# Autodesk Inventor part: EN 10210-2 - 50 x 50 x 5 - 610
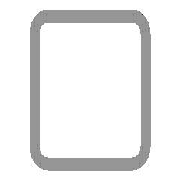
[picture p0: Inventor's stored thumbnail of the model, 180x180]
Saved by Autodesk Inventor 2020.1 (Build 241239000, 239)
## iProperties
IsCustomPart: 1
Created: 2019-01
Part Number: EN 10210-2 - 50 x 50 x 5 - 610
Material: Stahl, weich
Description: Rohrleitung
Document SubType Name: Modeling
Standard: DIN
Designer: lutzd
Standard Revision: 2006-07
Standards Organization: DIN
Language: de-DE
Size Designation: 50 x 50 x 5
Categories: <MemberInstance><Categories><Category DisplayName="Profile" InternalName="089c4875-fa83-4c05-b084-43b9cc11f5ed" Mnemonic="GRDR"><CategoryParameter DisplayName="
Stock Number: 50 x 50 x 5
Mass: 4175.75 g
Surface Area: 2083.96 cm^2
Volume: 531.943 cm^3
Density: 7.85 g/cm^3
Appearance: Halbpoliert
_CCFamilyMember: 16
_CCFamilyDisplayName: DIN EN 10210-2 (USAS B17.1 quadratisch) - Rohrleitung — In Klammern angegebene Größen wurden aufgehoben
_FrameMemberDoc: Frame Member File
_Version: 15.0.0
_GetPNFromCC: 1
G_L: 610,000 mm
G_W: 50,000 mm
G_H: 50,000 mm
DocNumber: ADSK-014142
Folder: .
Dimensions: 50x50x610 mm
Mass: 4,176 kg
+F1DF09DF-1374-4674-A909-8C9C65E2400E+SCHNITTDETAIL1: Schnittwinkel 90,00 grd
Title: Profil-Bauteil
Author: lutzd
Revision Number: -
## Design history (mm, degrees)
node "Startebene"
node "Endebene"
sketch "Skizze"
  geometry: L1 (-25, -17.5)-(-25, 17.5); L2 (-17.5, 25)-(17.5, 25); L3 (25, 17.5)-(25, -17.5); L4 (17.5, -25)-(-17.5, -25); L5 (-15, 20)-(15, 20); L6 (20, 15)-(20, -15); L7 (15, -20)-(-15, -20); L8 (-20, -15)-(-20, 15); L9 (0, 37.175)-(0, -37.175) reference; L10 (-37.175, 0)-(37.175, 0) reference; A1 r 7.5 centre (-17.5, -17.5) between (-25, -17.5) and (-17.5, -25); A2 r 7.5 centre (-17.5, 17.5) between (-17.5, 25) and (-25, 17.5); A3 r 7.5 centre (17.5, 17.5) between (25, 17.5) and (17.5, 25); A4 r 7.5 centre (17.5, -17.5) between (17.5, -25) and (25, -17.5); A5 r 5 centre (-15, -15) between (-20, -15) and (-15, -20); A6 r 5 centre (-15, 15) between (-15, 20) and (-20, 15); A7 r 5 centre (15, 15) between (20, 15) and (15, 20); A8 r 5 centre (15, -15) between (15, -20) and (20, -15)
  constraints: 16 end point, 16 point on circle, 16 tangent, 8 centre point, 6 equal radius, 4 parallel, 2 perpendicular, 2 other
  dimensions: "d7" = 7.5 radius of A1 (= G_IR); "d10" = 50 distance between parallel lines of L2 L4 (= G_H); "d11" = 50 distance between parallel lines of L1 L3 (= G_W); "d12" = 5 distance between parallel lines of L3 L6 (= G_T); "d15" = 25 distance between parallel lines of L2 L10 (= 0.5 x d10); "d16" = 25 distance between parallel lines of L9 L3 (= 0.5 x d11); "d19" = 5 radius of A5 (= G_T); "d20" = 5 distance between parallel lines of L4 L7 (= G_T)
extrude "Körper" new body sketch "Skizze" stored distance "d3" = 610 (= G_L); taper "d4" = 0 deg
node "Driven Length"
  sketch "Sketch3"
    geometry: L1 (0, 0)-(10, 0) reference
    constraints: 2 end point, 1 horizontal
  workplane "Work Plane3"
  sketch "Sketch4"
    geometry: L1 (-2, 25)-(12, 25) reference; L2 (-2, 635)-(12, 635) reference
    dimensions: "d18" = 610 distance between parallel lines of L1 L2 (derived)
workplane "Arbeitsebene4"
feature "Trennen1"
sketch "Skizze5"
  geometry: L1 (-35, 610)-(0, 610) reference; L2 (-17.5, 610)-(-17.5, 180); 3 further points
  constraints: 2 end point, 1 coincident, 1 midpoint, 1 point on line, 1 vertical
  dimensions: "d21" = 45 distance of point (-17.5, 225) point (-17.5, 180); "d22" = 385 distance from line of L1 point (-17.5, 225)
hole "Bohrung1" sketch "Skizze5" at (-17.5, 180), (-17.5, 225) diameter "d23" = 6.647; stored, may be unused: countersink angle "d27" = 90 deg, drill point angle "d29" = 118 deg; dims "d24" = 16, "d25" = 4, "d26" = 2, "d28" = 8
sketch "Skizze6"
  geometry: L1 (610, 35)-(610, 0) reference; L2 (610, 17.5)-(289, 17.5); 3 further points
  constraints: 2 end point, 1 coincident, 1 horizontal, 1 midpoint, 1 point on line
  dimensions: "d30" = 41 distance of point (330, 17.5) L2.end; "d31" = 280 distance from line of L1 point (330, 17.5)
hole "Bohrung2" sketch "Skizze6" at (289, 17.5), (330, 17.5) diameter "d32" = 6.647; stored, may be unused: countersink angle "d36" = 90 deg, drill point angle "d38" = 118 deg; dims "d33" = 16, "d34" = 4, "d35" = 2, "d37" = 8
body "Solid1"
other parameters: "G_W" = 50 [user parameter; used in 1 equation term], "G_H" = 50 [user parameter; used in 1 equation term], "G_T" = 5 [user parameter; used in 3 equation terms], "G_IR" = 7.5 [user parameter; used in 1 equation term], "G_L" = 610 (= d18) [user parameter; used in 1 equation term], "G_OFFSET_START" = -25 [user parameter; used in 1 equation term], "G_OFFSET_END" = 0 [user parameter; used in 1 equation term], "d13" = 25 (= -G_OFFSET_START), "d14" = 635 (= G_OFFSET_END + B_L), "B_L" = 635 [user parameter; used in 1 equation term], "d17" = 90 deg
